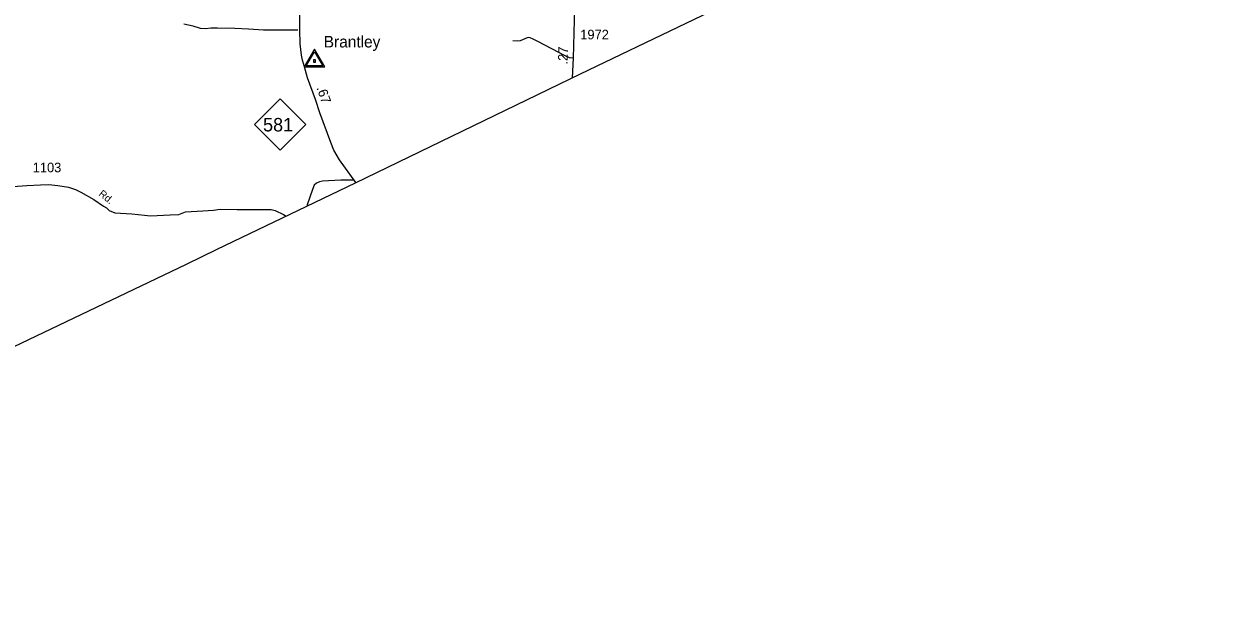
# Model space of a CAD drawing. Extents: x 2220236 to 2384410, y 720751 to 894131.
# Drawn here: x 2257585 to 2273033, y 726061 to 733739 of the extents above; entities that cross this region are included whole.
import ezdxf

# ---------------------------------------------------------------- set-up
doc = ezdxf.new("R2010")
doc.units = 0
doc.layers.add('Default', color=7, linetype='Continuous')

msp = doc.modelspace()

# ---------------------------------------------------------------- linework, layer by layer
at = {"layer": 'Default'}
for points in [[(2287877, 744178), (2270992, 736056), (2267562, 734406), (2264815, 733083), (2261891, 731668), (2260094, 730805), (2259694, 730607), (2256472, 729070), (2253954, 727878), (2253181, 727508), (2253078, 727457), (2253042, 727443), (2252978, 727424), (2252870, 727387), (2251763, 727086), (2250517, 726735), (2250148, 726626), (2248127, 726061)], [(2261903, 731674), (2261687, 731968), (2261617, 732097), (2261575, 732194), (2261435, 732583), (2261375, 732754), (2261274, 733038), (2261233, 733177), (2261209, 733266), (2261194, 733331), (2261176, 733477), (2261173, 733661), (2261174, 734557), (2261172, 734829), (2261161, 735037)], [(2264886, 734421), (2264850, 734315), (2264809, 734203), (2264782, 734113), (2264750, 734024), (2264744, 733918), (2264737, 733788), (2264724, 733293), (2264714, 733034)], [(2261147, 733655), (2260703, 733657), (2260504, 733669), (2260330, 733678), (2260101, 733683), (2260015, 733680), (2259953, 733672), (2259881, 733679), (2259788, 733706), (2259666, 733735)], [(2264724, 733293), (2264677, 733295), (2264622, 733324), (2264449, 733412), (2264265, 733507), (2264204, 733538), (2264169, 733556), (2264151, 733560), (2264128, 733556), (2264038, 733516), (2264003, 733512), (2263940, 733516)], [(2255005, 731875), (2255197, 731789), (2255405, 731711), (2255526, 731674), (2255756, 731645), (2255979, 731636), (2256612, 731596), (2256831, 731590), (2257038, 731594), (2257255, 731610), (2257624, 731634), (2257803, 731645), (2257909, 731647), (2258028, 731638), (2258167, 731616), (2258258, 731585), (2258328, 731548), (2258494, 731453), (2258620, 731369), (2258658, 731345), (2258695, 731311)], [(2261880, 731705), (2261708, 731705), (2261467, 731693), (2261427, 731683), (2261391, 731668), (2261361, 731642), (2261336, 731586), (2261268, 731385), (2261265, 731367)], [(2258695, 731311), (2258770, 731280), (2258991, 731267), (2259152, 731252), (2259232, 731243), (2259489, 731256), (2259602, 731261), (2259688, 731295), (2259911, 731307), (2260051, 731316), (2260137, 731329), (2260359, 731323), (2260565, 731325), (2260716, 731322), (2260800, 731323), (2260853, 731310), (2260959, 731261), (2260995, 731238)]]:
    msp.add_lwpolyline(points, dxfattribs=at)
for points in [[(2261497, 733181), (2261363, 733407), (2261230, 733181)], [(2261471, 733193), (2261256, 733193), (2261363, 733376)], [(2261376, 733240), (2261376, 733268), (2261351, 733268), (2261351, 733240)], [(2260586, 732428), (2260919, 732761), (2261252, 732428), (2260919, 732095)]]:
    msp.add_lwpolyline(points, close=True, dxfattribs=at)

# ---------------------------------------------------------------- texts
for s, height, p in [('1972', 125, (2264818, 733536)), ('Brantley', 150, (2261484, 733431)), ('581', 175, (2260695, 732339)), ('1103', 125, (2257701, 731808))]:
    msp.add_text(s, height=height, dxfattribs=at).set_placement(p)
for s, height, rotation, p in [('.27', 125, 88.4868, (2264653, 733208)), ('.67', 125, 289.3348, (2261388, 732906)), ('Rd.', 95, 321.1176, (2258551, 731513))]:
    msp.add_text(s, height=height, rotation=rotation, dxfattribs=at).set_placement(p)

doc.saveas('drawing.dxf')
